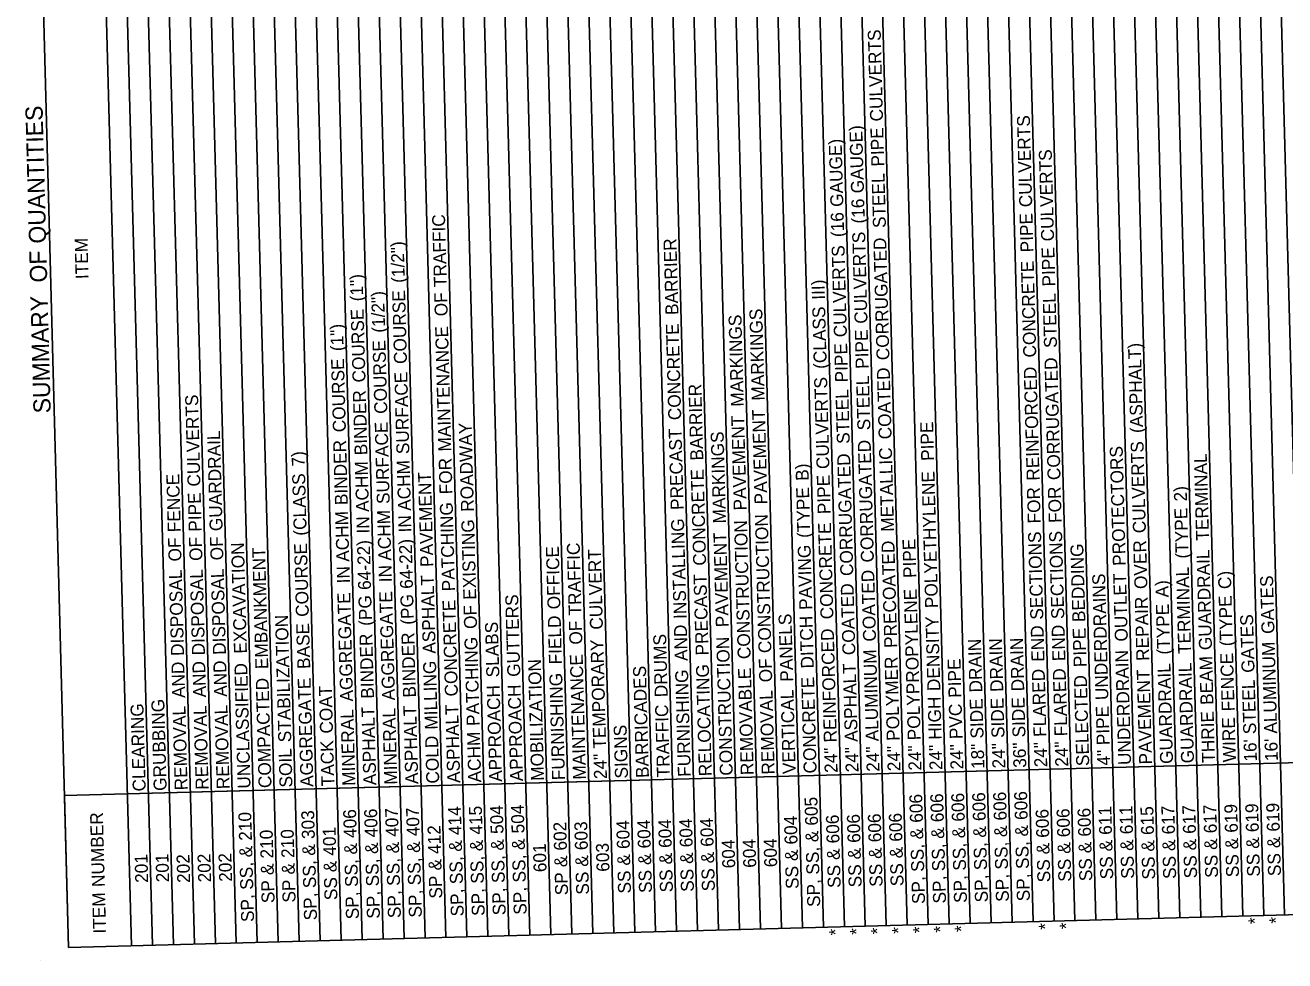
# Model space of a CAD drawing. Extents: x 1930091 to 1931962, y 596452 to 607874.
# Drawn here: x 1930091 to 1930677, y 606382 to 606818 of the extents above; entities that cross this region are included whole.
import ezdxf

# ---------------------------------------------------------------- set-up
doc = ezdxf.new("R2010")
doc.units = 0
doc.layers.add('Default', color=7, linetype='Continuous')
doc.layers.add('R_Border', color=7, linetype='Continuous')

msp = doc.modelspace()

# ---------------------------------------------------------------- linework, layer by layer
at = {"layer": 'Default'}
for p, q in [((1930589.12, 606401.48), (1930571.16, 607070.58)), ((1930598.87, 606401.74), (1930580.91, 607070.84)), ((1930608.61, 606402), (1930590.65, 607071.1)), ((1930618.36, 606402.27), (1930600.4, 607071.36)), ((1930628.11, 606402.53), (1930610.15, 607071.62)), ((1930637.85, 606402.79), (1930619.89, 607071.89)), ((1930647.6, 606403.05), (1930629.64, 607072.15)), ((1930657.35, 606403.31), (1930639.39, 607072.41)), ((1930667.09, 606403.57), (1930649.13, 607072.67)), ((1930676.84, 606403.84), (1930658.88, 607072.93)), ((1930686.59, 606404.1), (1930668.62, 607073.19)), ((1930364.95, 606395.46), (1930346.99, 607064.56)), ((1930374.7, 606395.73), (1930356.74, 607064.82)), ((1930384.44, 606395.99), (1930366.48, 607065.08)), ((1930394.19, 606396.25), (1930376.23, 607065.34)), ((1930403.94, 606396.51), (1930385.98, 607065.61)), ((1930413.68, 606396.77), (1930395.72, 607065.87)), ((1930423.43, 606397.03), (1930405.47, 607066.13)), ((1930433.18, 606397.3), (1930415.22, 607066.39)), ((1930442.92, 606397.56), (1930424.96, 607066.65)), ((1930452.67, 606397.82), (1930434.71, 607066.91)), ((1930462.42, 606398.08), (1930444.46, 607067.18)), ((1930472.16, 606398.34), (1930454.2, 607067.44)), ((1930481.91, 606398.6), (1930463.95, 607067.7)), ((1930491.66, 606398.86), (1930473.69, 607067.96)), ((1930501.4, 606399.13), (1930483.44, 607068.22)), ((1930511.15, 606399.39), (1930493.19, 607068.48)), ((1930520.9, 606399.65), (1930502.93, 607068.75)), ((1930530.64, 606399.91), (1930512.68, 607069.01)), ((1930540.39, 606400.17), (1930522.43, 607069.27)), ((1930550.14, 606400.43), (1930532.17, 607069.53)), ((1930559.88, 606400.7), (1930541.92, 607069.79)), ((1930569.63, 606400.96), (1930551.67, 607070.05)), ((1930579.37, 606401.22), (1930561.41, 607070.32)), ((1930150.53, 606389.71), (1930132.57, 607058.8)), ((1930160.28, 606389.97), (1930142.31, 607059.07)), ((1930170.02, 606390.23), (1930152.06, 607059.33)), ((1930179.77, 606390.49), (1930161.81, 607059.59)), ((1930189.52, 606390.75), (1930171.55, 607059.85)), ((1930199.26, 606391.02), (1930181.3, 607060.11)), ((1930209.01, 606391.28), (1930191.05, 607060.37)), ((1930218.75, 606391.54), (1930200.79, 607060.64)), ((1930228.5, 606391.8), (1930210.54, 607060.9)), ((1930238.25, 606392.06), (1930220.29, 607061.16)), ((1930247.99, 606392.32), (1930230.03, 607061.42)), ((1930257.74, 606392.59), (1930239.78, 607061.68)), ((1930267.49, 606392.85), (1930249.53, 607061.94)), ((1930277.23, 606393.11), (1930259.27, 607062.21)), ((1930286.98, 606393.37), (1930269.02, 607062.47)), ((1930296.73, 606393.63), (1930278.77, 607062.73)), ((1930306.47, 606393.89), (1930288.51, 607062.99)), ((1930316.22, 606394.16), (1930298.26, 607063.25)), ((1930325.97, 606394.42), (1930308, 607063.51)), ((1930335.71, 606394.68), (1930317.75, 607063.78)), ((1930345.46, 606394.94), (1930327.5, 607064.04)), ((1930355.21, 606395.2), (1930337.24, 607064.3)), ((1930111.54, 606388.66), (1930093.58, 607057.76)), ((1930140.78, 606389.45), (1930122.82, 607058.54)), ((1930938.1, 606481.56), (1930109.65, 606459.32)), ((1930938.1, 606481.56), (1930138.89, 606460.11)), ((1930111.54, 606388.66), (1930109.65, 606459.32)), ((1931105.69, 606415.35), (1930111.54, 606388.66)), ((1931105.69, 606415.35), (1930111.54, 606388.66))]:
    msp.add_line(p, q, dxfattribs=at)
at = {"layer": 'R_Border'}
msp.add_line((1930098.54, 606382.46), (1930098.54, 606382.46), dxfattribs=at)

# ---------------------------------------------------------------- texts
at = {"layer": 'Default'}
for s, height, p in [(' CULVERTS', 6, (1930490.23, 606770.69)), (' QUANTITIES', 8, (1930101.23, 606713.16)), (' CULVERTS', 6, (1930559.57, 606730.8)), (' GAUGE)', 6, (1930481.37, 606737.26)), (' PIPE', 6, (1930490.79, 606749.71)), (' GAUGE)', 6, (1930471.79, 606730.96)), (' CULVERTS', 6, (1930569.75, 606714.92)), (' STEEL', 6, (1930491.56, 606721.13)), (' (16', 6, (1930481.75, 606723.21)), (' TRAFFIC', 6, (1930287.47, 606693.65)), (' (16', 6, (1930472.16, 606716.91)), (' PIPE', 6, (1930560.14, 606709.82)), (' CULVERTS', 6, (1930483, 606676.61)), ('ITEM', 6, (1930120.83, 606699.6)), (' (1/2")', 6, (1930267.91, 606695.62)), (' BARRIER', 6, (1930395.11, 606680.67)), (' CULVERTS', 6, (1930473.42, 606670.31)), (' CORRUGATED', 6, (1930493.21, 606659.64)), (' PIPE', 6, (1930570.32, 606693.94)), (' OF', 8, (1930101.72, 606695.05)), (' CONCRETE', 6, (1930561.45, 606660.91)), (' (1")', 6, (1930248.64, 606687.04)), (' III)', 6, (1930463.19, 606687.78)), (' SUMMARY', 8, (1930103.35, 606634.2)), (' (1/2")', 6, (1930258.78, 606672.44)), (' COURSE', 6, (1930268.93, 606657.88)), (' OF', 6, (1930287.84, 606680.07)), (' STEEL', 6, (1930571.08, 606665.36)), (' COURSE', 6, (1930249.65, 606649.3)), (' MARKINGS', 6, (1930435.19, 606640.85)), (' (CLASS', 6, (1930464.06, 606655.62)), (' (1")', 6, (1930239.5, 606663.87)), (' CONCRETE', 6, (1930396.42, 606631.76)), (' MARKINGS', 6, (1930425.51, 606638.04)), (' MAINTENANCE', 6, (1930289.53, 606617.18)), (' PIPE', 6, (1930483.56, 606655.63)), (' COURSE', 6, (1930259.79, 606634.7)), (' PIPE', 6, (1930473.98, 606649.33)), (' (ASPHALT)', 6, (1930611.16, 606625.79)), (' COURSE', 6, (1930240.52, 606626.13)), (' CORRUGATED', 6, (1930572.73, 606603.88)), (' SURFACE', 6, (1930270.05, 606615.95)), (' COATED', 6, (1930494.2, 606622.84)), (' REINFORCED', 6, (1930562.99, 606603.62)), (' BARRIER', 6, (1930406.68, 606612.99)), (' CULVERTS', 6, (1930465.31, 606609.03)), (' STEEL', 6, (1930484.33, 606627.05)), (' CULVERTS', 6, (1930172.92, 606600.87)), (' BINDER', 6, (1930250.56, 606615.43)), (' STEEL', 6, (1930474.75, 606620.75)), (' PAVEMENT', 6, (1930436.49, 606592.58)), (' SURFACE', 6, (1930260.92, 606592.77)), (' ROADWAY', 6, (1930300.03, 606589.15)), (' PAVEMENT', 6, (1930426.81, 606589.77)), (' PIPE', 6, (1930513.97, 606612.83)), (' GUARDRAIL', 6, (1930183.23, 606580.15)), (' PRECAST', 6, (1930397.54, 606590.01)), (' MARKINGS', 6, (1930417.22, 606583.73)), (' BINDER', 6, (1930241.43, 606592.25)), (' CORRUGATED', 6, (1930485.98, 606565.57)), (' METALLIC', 6, (1930495.35, 606579.87)), (' PROTECTORS', 6, (1930603.06, 606564.02)), (' CULVERTS', 6, (1930612.41, 606579.19)), (' 7)', 6, (1930221.44, 606610.19)), (' ACHM', 6, (1930251.27, 606589.05)), (' ACHM', 6, (1930270.76, 606589.58)), (' FOR', 6, (1930290.06, 606597.28)), (' CORRUGATED', 6, (1930476.4, 606559.27)), (' TERMINAL', 6, (1930641.76, 606575.73)), (' FENCE', 6, (1930163.74, 606579.63)), (' (CLASS', 6, (1930222.3, 606578.03)), (' PAVEMENT', 6, (1930281.21, 606563.49)), (' CONCRETE', 6, (1930407.99, 606564.08)), (' B)', 6, (1930455.7, 606603.56)), (' PIPE', 6, (1930465.87, 606588.05)), (' POLYETHYLENE', 6, (1930515.81, 606544.34)), (' (TYPE', 6, (1930456.41, 606577)), (' FOR', 6, (1930563.52, 606583.71)), (' FOR', 6, (1930573.27, 606583.98)), (' 2)', 6, (1930631.52, 606593.96)), (' PIPE', 6, (1930173.48, 606579.89)), (' ACHM', 6, (1930242.13, 606565.88)), (' ACHM', 6, (1930261.63, 606566.4)), (' PATCHING', 6, (1930291.27, 606552.17)), (' (TYPE', 6, (1930632.23, 606567.4)), (' IN', 6, (1930251.54, 606579.03)), (' IN', 6, (1930271.03, 606579.55)), (' EXISTING', 6, (1930301.13, 606548.23)), (' INSTALLING', 6, (1930398.9, 606539.31)), (' CONSTRUCTION', 6, (1930428.67, 606520.62)), (' CONSTRUCTION', 6, (1930438.34, 606523.43)), (' CONCRETE', 6, (1930467.18, 606539.14)), (' OF', 6, (1930164.1, 606566.05)), (' OF', 6, (1930173.85, 606566.31)), (' OF', 6, (1930183.6, 606566.57)), (' PAVEMENT', 6, (1930418.51, 606535.46)), (' PIPE', 6, (1930505.68, 606558.37)), (' SECTIONS', 6, (1930564.72, 606538.98)), (' SECTIONS', 6, (1930574.47, 606539.24)), (' EXCAVATION', 6, (1930194.51, 606523.18)), (' EMBANKMENT', 6, (1930204.46, 606515.98)), (' COURSE', 6, (1930223.31, 606540.29)), (' 64-22)', 6, (1930252.24, 606552.8)), (' 64-22)', 6, (1930271.73, 606553.32)), (' OFFICE', 6, (1930340.26, 606543.79)), (' TRAFFIC', 6, (1930350.09, 606540.94)), (' CULVERT', 6, (1930360.02, 606534.32)), (' PAVING', 6, (1930457.31, 606543.52)), (' PRECOATED', 6, (1930496.8, 606525.83)), (' BEDDING', 6, (1930584.26, 606537.86)), (' OVER', 6, (1930613.11, 606553.23)), (' GUARDRAIL', 6, (1930643.13, 606524.8)), (' DISPOSAL', 6, (1930165.28, 606522.1)), (' DISPOSAL', 6, (1930175.03, 606522.36)), (' DISPOSAL', 6, (1930184.77, 606522.62)), (' IN', 6, (1930242.4, 606555.86)), (' IN', 6, (1930261.9, 606556.38)), (' ASPHALT', 6, (1930282.3, 606523.13)), (' PRECAST', 6, (1930409.11, 606522.33)), (' COATED', 6, (1930486.97, 606528.76)), (' UNDERDRAINS', 6, (1930594.99, 606501.57)), (' OUTLET', 6, (1930604.01, 606528.8)), (' TERMINAL', 6, (1930633.43, 606522.99)), (' C)', 6, (1930652.12, 606553.2)), (' GATES', 6, (1930672.19, 606532.36)), (' COATED', 6, (1930477.38, 606522.46)), (' POLYPROPYLENE', 6, (1930507.71, 606482.89)), (' A)', 6, (1930622.97, 606549.29)), (' AGGREGATE', 6, (1930243.88, 606500.88)), (' (PG', 6, (1930252.69, 606536.1)), (' AGGREGATE', 6, (1930263.37, 606501.41)), (' (PG', 6, (1930272.18, 606536.62)), (' CONCRETE', 6, (1930292.58, 606503.26)), (' GUTTERS', 6, (1930321.6, 606512.39)), (' REPAIR', 6, (1930614, 606519.81)), (' (TYPE', 6, (1930652.84, 606526.63)), (' OF', 6, (1930301.49, 606534.65)), (' PANELS', 6, (1930448.46, 606510.11)), (' (TYPE', 6, (1930623.68, 606522.73)), (' STABILIZATION', 6, (1930215.13, 606481.94)), (' BASE', 6, (1930223.97, 606516.05)), (' SLABS', 6, (1930311.85, 606512.12)), (' FIELD', 6, (1930340.95, 606518.17)), (' OF', 6, (1930350.46, 606527.36)), (' AND', 6, (1930399.43, 606519.74)), (' DITCH', 6, (1930458.04, 606516.27)), (' DENSITY', 6, (1930516.85, 606505.76)), (' END', 6, (1930565.25, 606519.41)), (' END', 6, (1930574.99, 606519.67)), (' GATES', 6, (1930662.92, 606514.28)), (' BINDER', 6, (1930253.6, 606502.22)), (' BINDER', 6, (1930273.09, 606502.74)), (' PATCHING', 6, (1930302.7, 606489.54)), (' TEMPORARY', 6, (1930361.51, 606478.97)), (' DRUMS', 6, (1930390.13, 606502.9)), ('CONSTRUCTION', 6, (1930420.31, 606468.64)), (' REINFORCED', 6, (1930468.72, 606481.85)), (' DRAIN', 6, (1930546.12, 606505.38)), (' DRAIN', 6, (1930555.86, 606505.64)), (' PIPE', 6, (1930584.82, 606516.89)), (' ALUMINUM', 6, (1930488.21, 606482.37)), (' DRAIN', 6, (1930536.37, 606505.12)), ('UNDERDRAIN', 6, (1930605.49, 606473.61)), (' ALUMINUM', 6, (1930673.43, 606485.96)), (' AND', 6, (1930165.81, 606502.52)), (' AND', 6, (1930175.55, 606502.78)), (' AND', 6, (1930185.3, 606503.05)), ('UNCLASSIFIED', 6, (1930196.14, 606462.62)), (' MILLING', 6, (1930283.24, 606487.81)), ('MOBILIZATION', 6, (1930332.59, 606466.28)), ('MAINTENANCE', 6, (1930352.08, 606466.81)), (' OF', 6, (1930438.71, 606509.85)), (' ASPHALT', 6, (1930478.47, 606482.11)), (' POLYMER', 6, (1930497.96, 606482.63)), (' PIPE', 6, (1930526.68, 606502.64)), ('GUARDRAIL', 6, (1930624.98, 606474.13)), ('GUARDRAIL', 6, (1930634.73, 606474.39)), (' BEAM', 6, (1930643.81, 606499.35)), (' FENCE', 6, (1930653.65, 606496.35)), ('FURNISHING', 6, (1930342.34, 606466.54)), ('BARRICADES', 6, (1930381.32, 606467.59)), ('FURNISHING', 6, (1930400.82, 606468.11)), ('RELOCATING', 6, (1930410.56, 606468.38)), ('REMOVABLE', 6, (1930430.05, 606468.9)), ('CONCRETE', 6, (1930459.29, 606469.68)), (' FLARED', 6, (1930566.19, 606484.46)), (' FLARED', 6, (1930575.93, 606484.72)), ('SELECTED', 6, (1930586, 606473.09)), ('PAVEMENT', 6, (1930615.24, 606473.87)), ('COMPACTED', 6, (1930205.89, 606462.88)), ('AGGREGATE', 6, (1930225.38, 606463.41)), (' COAT', 6, (1930234.53, 606486)), ('APPROACH', 6, (1930313.1, 606465.76)), ('APPROACH', 6, (1930322.84, 606466.02)), ('VERTICAL', 6, (1930449.55, 606469.42)), (' STEEL', 6, (1930663.69, 606485.7)), ('GRUBBING', 6, (1930157.15, 606461.57)), ('REMOVAL', 6, (1930439.8, 606469.16)), (' HIGH', 6, (1930517.45, 606483.15)), (' SIDE', 6, (1930536.95, 606483.68)), (' SIDE', 6, (1930546.69, 606483.94)), (' SIDE', 6, (1930556.44, 606484.2)), ('CLEARING', 6, (1930147.41, 606461.31)), ('REMOVAL', 6, (1930166.9, 606461.84)), ('REMOVAL', 6, (1930176.65, 606462.1)), ('REMOVAL', 6, (1930186.39, 606462.36)), ('MINERAL', 6, (1930244.87, 606463.93)), ('ASPHALT', 6, (1930254.62, 606464.19)), ('MINERAL', 6, (1930264.36, 606464.45)), ('ASPHALT', 6, (1930274.11, 606464.71)), ('ASPHALT', 6, (1930293.6, 606465.24)), ('TRAFFIC', 6, (1930391.07, 606467.85)), (' PVC', 6, (1930527.2, 606483.42)), (' PIPE', 6, (1930595.55, 606480.59)), ('THRIE', 6, (1930644.48, 606474.66)), ('SIGNS', 6, (1930371.58, 606467.33)), ('WIRE', 6, (1930654.22, 606474.92)), ('TACK', 6, (1930235.12, 606463.67)), ('COLD', 6, (1930283.86, 606464.97)), ('ACHM', 6, (1930303.35, 606465.5)), ("16'", 6, (1930663.97, 606475.18)), ("16'", 6, (1930673.72, 606475.44)), ('SOIL', 6, (1930215.63, 606463.14)), ('24"', 6, (1930469.04, 606469.95)), ('24"', 6, (1930478.79, 606470.21)), ('24"', 6, (1930488.53, 606470.47)), ('24"', 6, (1930498.28, 606470.73)), ('24"', 6, (1930508.03, 606470.99)), ('24"', 6, (1930517.77, 606471.25)), ('24"', 6, (1930527.52, 606471.52)), ('18"', 6, (1930537.27, 606471.78)), ('24"', 6, (1930547.01, 606472.04)), ('36"', 6, (1930556.76, 606472.3)), ('24"', 6, (1930566.51, 606472.56)), ('24"', 6, (1930576.25, 606472.82)), ('4"', 6, (1930595.75, 606473.35)), ('24"', 6, (1930361.83, 606467.07)), (' 605', 6, (1930460.01, 606443.18)), (' 606', 6, (1930508.74, 606444.52)), (' 606', 6, (1930518.48, 606444.78)), (' 606', 6, (1930528.23, 606445.04)), (' 606', 6, (1930537.98, 606445.3)), (' 606', 6, (1930547.72, 606445.56)), (' 606', 6, (1930557.47, 606445.82)), (' 619', 6, (1930674.66, 606440.4)), (' NUMBER', 6, (1930128.48, 606414.64)), (' 210', 6, (1930196.85, 606436.15)), (' 303', 6, (1930226.09, 606436.93)), (' 406', 6, (1930245.58, 606437.45)), (' 406', 6, (1930255.33, 606437.71)), (' 407', 6, (1930265.08, 606437.97)), (' 407', 6, (1930274.82, 606438.24)), (' 414', 6, (1930294.31, 606438.77)), (' 415', 6, (1930304.06, 606439)), (' 504', 6, (1930313.81, 606439.3)), (' 504', 6, (1930323.55, 606439.56)), (' 604', 6, (1930450.49, 606434.4)), (' 606', 6, (1930469.98, 606434.91)), (' 606', 6, (1930479.73, 606435.18)), (' 606', 6, (1930489.47, 606435.44)), (' 606', 6, (1930499.22, 606435.7)), (' 606', 6, (1930567.45, 606437.53)), (' 606', 6, (1930577.19, 606437.79)), (' 606', 6, (1930586.94, 606438.05)), (' 611', 6, (1930596.67, 606438.9)), (' 611', 6, (1930606.42, 606439.16)), (' 615', 6, (1930616.18, 606438.82)), (' 617', 6, (1930625.92, 606439.1)), (' 617', 6, (1930635.67, 606439.36)), (' 617', 6, (1930645.42, 606439.62)), (' 619', 6, (1930655.16, 606439.88)), (' 619', 6, (1930664.91, 606440.14)), (' 401', 6, (1930236.05, 606429.21)), (' 412', 6, (1930284.8, 606430.01)), (' 602', 6, (1930343.27, 606431.58)), (' 603', 6, (1930353.02, 606431.77)), (' 604', 6, (1930372.52, 606432.31)), (' 604', 6, (1930382.26, 606432.57)), (' 604', 6, (1930392.01, 606432.83)), (' 604', 6, (1930401.76, 606433.1)), (' 604', 6, (1930411.5, 606433.36)), (' &', 6, (1930508.94, 606436.79)), (' &', 6, (1930518.69, 606437.05)), (' &', 6, (1930528.44, 606437.31)), (' &', 6, (1930538.18, 606437.57)), (' &', 6, (1930547.93, 606437.84)), (' &', 6, (1930557.68, 606438.1)), (' 210', 6, (1930206.82, 606427.9)), (' 210', 6, (1930216.57, 606428.16)), (' &', 6, (1930294.52, 606431.05)), (' &', 6, (1930304.27, 606431.27)), (' &', 6, (1930314.01, 606431.57)), (' &', 6, (1930323.76, 606431.83)), ('604', 6, (1930421.46, 606425.55)), ('604', 6, (1930431.21, 606425.81)), ('604', 6, (1930440.96, 606426.07)), (' &', 6, (1930460.21, 606435.46)), (' &', 6, (1930596.88, 606431.17)), (' &', 6, (1930606.62, 606431.43)), (' &', 6, (1930616.39, 606431.09)), (' &', 6, (1930626.13, 606431.37)), (' &', 6, (1930635.88, 606431.64)), (' &', 6, (1930645.63, 606431.9)), (' &', 6, (1930655.37, 606432.15)), (' &', 6, (1930665.12, 606432.42)), (' &', 6, (1930674.86, 606432.68)), ('202', 6, (1930187.55, 606419.29)), (' &', 6, (1930197.06, 606428.43)), (' &', 6, (1930226.3, 606429.2)), (' &', 6, (1930245.79, 606429.73)), (' &', 6, (1930255.54, 606429.99)), (' &', 6, (1930265.28, 606430.25)), (' &', 6, (1930275.03, 606430.51)), ('601', 6, (1930333.73, 606423.76)), ('603', 6, (1930362.99, 606423.96)), (' &', 6, (1930382.47, 606424.85)), (' &', 6, (1930392.22, 606425.11)), (' &', 6, (1930401.96, 606425.37)), (' &', 6, (1930411.71, 606425.63)), (' &', 6, (1930450.7, 606426.68)), (' SS,', 6, (1930460.62, 606420.37)), (' &', 6, (1930470.19, 606427.19)), (' &', 6, (1930479.94, 606427.45)), (' &', 6, (1930489.68, 606427.71)), (' &', 6, (1930499.43, 606427.97)), (' SS,', 6, (1930509.35, 606421.7)), (' SS,', 6, (1930519.1, 606421.96)), (' SS,', 6, (1930528.84, 606422.22)), (' SS,', 6, (1930538.59, 606422.48)), (' SS,', 6, (1930548.34, 606422.75)), (' SS,', 6, (1930558.08, 606423.01)), (' &', 6, (1930567.65, 606429.8)), (' &', 6, (1930577.4, 606430.07)), (' &', 6, (1930587.15, 606430.33)), ('SS', 6, (1930675.15, 606421.93)), ('201', 6, (1930148.55, 606418.79)), ('201', 6, (1930158.29, 606419.05)), ('202', 6, (1930168.06, 606418.76)), ('202', 6, (1930177.8, 606419.03)), (' SS,', 6, (1930197.46, 606413.34)), (' &', 6, (1930207.03, 606420.17)), (' &', 6, (1930216.78, 606420.43)), (' SS,', 6, (1930226.7, 606414.11)), (' &', 6, (1930236.26, 606421.49)), (' SS,', 6, (1930246.19, 606414.64)), (' SS,', 6, (1930255.94, 606414.9)), (' SS,', 6, (1930265.69, 606415.16)), (' SS,', 6, (1930275.43, 606415.42)), (' &', 6, (1930285, 606422.29)), (' SS,', 6, (1930294.93, 606415.96)), (' SS,', 6, (1930304.67, 606416.18)), (' SS,', 6, (1930314.42, 606416.48)), (' SS,', 6, (1930324.17, 606416.74)), (' &', 6, (1930343.48, 606423.85)), (' &', 6, (1930353.23, 606424.05)), (' &', 6, (1930372.72, 606424.59)), ('SS', 6, (1930470.48, 606416.44)), ('SS', 6, (1930480.22, 606416.71)), ('SS', 6, (1930489.97, 606416.97)), ('SS', 6, (1930499.72, 606417.23)), ('SS', 6, (1930567.94, 606419.06)), ('SS', 6, (1930577.69, 606419.32)), ('SS', 6, (1930587.43, 606419.58)), ('SS', 6, (1930597.17, 606420.43)), ('SS', 6, (1930606.91, 606420.69)), ('SS', 6, (1930616.67, 606420.35)), ('SS', 6, (1930626.42, 606420.63)), ('SS', 6, (1930636.17, 606420.89)), ('SS', 6, (1930645.91, 606421.15)), ('SS', 6, (1930655.66, 606421.41)), ('SS', 6, (1930665.41, 606421.67)), ('SS', 6, (1930236.55, 606410.75)), ('SP', 6, (1930285.29, 606411.47)), ('SP', 6, (1930343.77, 606413.04)), ('SS', 6, (1930353.52, 606413.3)), ('SS', 6, (1930373.01, 606413.84)), ('SS', 6, (1930382.76, 606414.1)), ('SS', 6, (1930392.5, 606414.37)), ('SS', 6, (1930402.25, 606414.63)), ('SS', 6, (1930412, 606414.89)), ('SS', 6, (1930450.98, 606415.94)), ('SP,', 6, (1930509.69, 606408.94)), ('SP,', 6, (1930519.44, 606409.2)), ('SP,', 6, (1930529.19, 606409.46)), ('SP,', 6, (1930538.93, 606409.72)), ('SP,', 6, (1930548.68, 606409.98)), ('SP,', 6, (1930558.42, 606410.24)), ('SP', 6, (1930207.32, 606409.36)), ('SP', 6, (1930217.07, 606409.62)), ('SP,', 6, (1930266.03, 606402.39)), ('SP,', 6, (1930275.78, 606402.66)), ('SP,', 6, (1930295.27, 606403.19)), ('SP,', 6, (1930305.02, 606403.42)), ('SP,', 6, (1930314.76, 606403.72)), ('SP,', 6, (1930324.51, 606403.98)), ('SP,', 6, (1930460.96, 606407.6)), ('ITEM', 6, (1930129, 606395.22)), ('SP,', 6, (1930197.8, 606400.57)), ('SP,', 6, (1930227.04, 606401.35)), ('SP,', 6, (1930246.54, 606401.87)), ('SP,', 6, (1930256.28, 606402.13)), ('*', 6, (1930471.07, 606394.37)), ('*', 6, (1930480.82, 606394.63)), ('*', 6, (1930490.56, 606394.89)), ('*', 6, (1930500.31, 606395.15)), ('*', 6, (1930510.06, 606395.41)), ('*', 6, (1930519.8, 606395.68)), ('*', 6, (1930529.55, 606395.94)), ('*', 6, (1930568.53, 606396.98)), ('*', 6, (1930578.28, 606397.25)), ('*', 6, (1930666, 606399.6)), ('*', 6, (1930675.75, 606399.86))]:
    msp.add_text(s, height=height, rotation=91.53769, dxfattribs=at).set_placement(p)

doc.saveas('drawing.dxf')
